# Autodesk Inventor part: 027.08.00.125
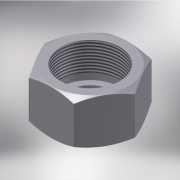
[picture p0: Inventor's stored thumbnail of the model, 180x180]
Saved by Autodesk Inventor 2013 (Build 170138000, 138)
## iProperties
Shininess: 25.0
Length Units: 11269
Angle Units: 11279
Time Units: 11290
Mass Units: 11283
Length Display Precision: 3
Angle Display Precision: 2
Created: 2001-11
Part Number: 027.08.00.125
Document SubType Name: Modeling
Designer: SOleg
Material: Steel, Mild
Density: 7.86 g/cm^3
Density: 0.0
Volumn: 0.0
Area: 0.0
PropertySet Name: Model Information
Control State: 0
Master: False
Checked Out: False
Checked Out Date: 2008-10-15
Last Check In Date: 2008-10-15
Author: SOleg
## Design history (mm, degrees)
sketch "Sketch1"
  geometry: L1 (144.878, 170.5)-(113.123, 170.5); L2 (160.758, 143.006)-(144.878, 170.5); L3 (144.88, 115.5)-(160.758, 143.006); L4 (113.13, 115.5)-(144.88, 115.5); L5 (97.248, 142.999)-(113.13, 115.5); L6 (113.123, 170.5)-(97.248, 142.999)
  constraints: 12 end point, 2 horizontal, 2 parallel, 1 other
  dimensions: "d1" = 63.51 distance of L2.start L5.start; "d3" = 55 distance of L1.start L3.start; "d5" = 55 distance of L5.start L1.start; "d7" = 63.51 distance of L3.start L1.end; "d9" = 55 distance of L3.start L5.start; "d11" = 31.75 distance of L4.start L3.start
extrude "ExtrusionBlind1" new body sketch "Sketch1" distance "d12" = 32; taper "d13" = 0 deg
node "WorkPlane1"
sketch "Sketch2"
  geometry: C1 r 17 at (-129.004, 143.001)
  constraints: 1 centre point
  dimensions: "d16" = 34 diameter of C1
extrude "ExtrusionBlind2" cut sketch "Sketch2" distance "d17" = 7; taper "d18" = 0 deg
node "WorkAxis1"
sketch "Sketch3"
  geometry: C1 r 21.5 at (0, 0)
  constraints: 1 centre point
  dimensions: "d21" = 43 diameter of C1
extrude "ExtrusionBlind3" cut sketch "Sketch3" distance "d22" = 5; taper "d23" = 0 deg
extrude "ExtrusionBlind4" cut distance "d27" = 30; taper "d28" = 0 deg
  node "Sketch4" dims "d26" = 42
sketch "Sketch5"
  geometry: L1 (0, -31.755)-(-32, -31.755); L2 (0, -4.755)-(0, -31.755); L3 (-4.619, 3.245)-(0, -4.755); L4 (-27.381, 3.245)-(-4.619, 3.245); L5 (-32, -4.755)-(-27.381, 3.245); L6 (-32, -31.755)-(-32, -4.755); L7 (-61.639, -31.755)-(29.639, -31.755); 1 further point
  constraints: 14 end point, 2 horizontal, 2 vertical
  dimensions: "d30" = 32 distance of L1.start L1.end; "d32" = 0 horizontal distance of L1.end point (-32, 0); "d34" = 150 deg angle of L6 L5; "d36" = 150 deg angle of L3 L2; "d38" = 27 distance of L2.start L1.start; "d40" = 35 vertical distance of L4.start L1.end
revolve "RevolutionAngle1" sketch "Sketch5" stored, may be unused: angle "d41" = 360 deg
thread "Thread1" dims "d42" = 10, "d43" = 0
body "Solid1"
other parameters: "d0" = 63.51 (derived), "d2" = 55 (derived), "d4" = 55 (derived), "d6" = 63.51 (derived), "d8" = 55 (derived), "d10" = 31.75 (derived), "d14" = 0, "d15" = 34 (derived), "d19" = 0, "d20" = 43 (derived), "d24" = 0, "d25" = 42 (derived), "d29" = 32 (derived), "d31" = 0 (derived), "d33" = 150 deg (derived), "d35" = 150 deg (derived), "d37" = 27 (derived), "d39" = 35 (derived)
